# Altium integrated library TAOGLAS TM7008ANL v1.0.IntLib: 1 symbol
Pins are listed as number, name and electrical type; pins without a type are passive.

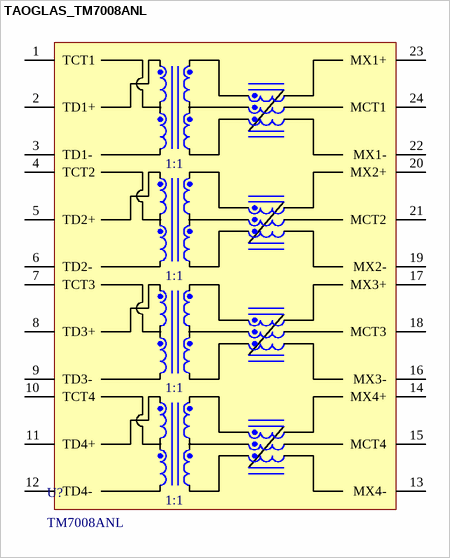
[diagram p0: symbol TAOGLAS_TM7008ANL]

## TAOGLAS_TM7008ANL
designator U?, comment TM7008ANL
10G Base-T transformer Single Port and 24pin SMT with PoE+; ComponentLibStatus: Created; MFG: Taoglas; Temp_High: +85C; Temp_Low: -40C
footprint TAOGLAS_TM7008ANL (10G Base-T transformer Single Port and 24pin SMT with PoE+)
pins: 1 TCT1, 2 TD1+, 3 TD1-, 4 TCT2, 5 TD2+, 6 TD2-, 7 TCT3, 8 TD3+, 9 TD3-, 10 TCT4, 11 TD4+, 12 TD4-, 13 MX4-, 14 MX4+, 15 MCT4, 16 MX3-, 17 MX3+, 18 MCT3, 19 MX2-, 20 MX2+, 21 MCT2, 22 MX1-, 23 MX1+, 24 MCT1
